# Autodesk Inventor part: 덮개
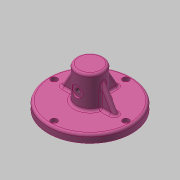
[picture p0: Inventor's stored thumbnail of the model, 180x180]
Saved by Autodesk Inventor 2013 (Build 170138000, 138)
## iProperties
Created: 2017-08
Part Number: 덮개
Material: 알루미늄 6061
Document SubType Name: Modeling
Designer: mduedu
Density: 2.71 g/cm^3
Mass: 336.253 g
Surface Area: 314.323 cm^2
Volume: 124.079 cm^3
Author: mduedu
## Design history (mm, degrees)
sketch "스케치1"
  geometry: C1 r 52.5 at (0, 0); 1 further point
  constraints: 1 centre point, 1 coincident
  dimensions: "d55" = 105 diameter of C1
extrude "돌출1" new body sketch "스케치1" distance "d5" = 10; taper "d6" = 0 deg
sketch "스케치2"
  geometry: C1 r 17 at (0, 0); 1 further point
  constraints: 1 centre point, 1 coincident
  dimensions: "d74" = 34 diameter of C1
extrude "돌출2" join sketch "스케치2" distance "d9" = 40; taper "d10" = 0 deg
sketch "스케치3"
  geometry: C1 r 37 at (0, 0); 1 further point
  constraints: 1 centre point, 1 coincident
  dimensions: "d56" = 74 diameter of C1
extrude "돌출3" join sketch "스케치3" distance "d12" = 8; taper "d13" = 0 deg
sketch "스케치4"
  geometry: C1 r 33 at (0, 0); 1 further point
  constraints: 1 centre point, 1 coincident
  dimensions: "d57" = 66 diameter of C1
extrude "돌출4" cut sketch "스케치4" distance "d16" = 7; taper "d17" = 0 deg
sketch "스케치5"
  geometry: C1 r 9 at (0, 0); 1 further point
  constraints: 1 centre point, 1 coincident
  dimensions: "d18" = 18 diameter of C1
extrude "돌출5" cut sketch "스케치5" distance "d19" = 47; taper "d20" = 0 deg
node "작업 평면1"
sketch "스케치11"
  geometry: L1 (-52.5, -10)-(52.5, -10) reference; 2 further points
  constraints: 1 vertical alignment
  dimensions: "d78" = 28 distance from line of point (0, 18) L1
hole "구멍5" sketch "스케치11" at (0, 18) diameter "d79" = 5.917; stored, may be unused: countersink angle "d83" = 90 deg, drill point angle "d85" = 118 deg; dims "d80" = 6, "d81" = 14, "d82" = 2, "d84" = 8
fillet "모깎기9" dims "d86" = 3
fillet "모깎기5" dims "d40" = 1
sketch "스케치12"
  geometry: C1 r 2.5 at (0, 0); 1 further point
  constraints: 1 centre point, 1 coincident
  dimensions: "d87" = 5 diameter of C1
extrude "돌출6" join sketch "스케치12" distance "d88" = 3; taper "d89" = 0 deg
fillet "모깎기10" dims "d91" = 1
chamfer "모따기1" distance "d41" = 1; stored, may be unused: second distance "d42" = 2, angle "d43" = 45 deg
fillet "모깎기7" dims "d45" = 3
fillet "모깎기8" dims "d46" = 3
sketch "스케치10" dims "d59" = 90
  geometry: 3 further points
  constraints: 2 vertical alignment, 1 coincident, 2 other
hole "구멍4" sketch "스케치10" at (0, 45) diameter "d60" = 4.5; stored, may be unused: countersink angle "d64" = 90 deg, drill point angle "d66" = 118 deg; dims "d61" = 6, "d62" = 8, "d63" = 4.6, "d65" = 8
sketch "스케치13"
  geometry: L1 (52.5, 7)-(52.5, 0) reference; L2 (52.5, 0)-(47.25, 0) reference; L3 (47.25, 0)-(47.25, 5.4) reference; L4 (47.25, 5.4)-(49, 5.4) reference; L5 (49, 5.4)-(49, 10) reference; L6 (49, 10)-(49.5, 10) reference; L7 (-49.5, 10)-(-49, 10) reference; L8 (-49, 10)-(-49, 5.4) reference; L9 (-49, 5.4)-(-47.25, 5.4) reference; L10 (-47.25, 5.4)-(-47.25, 0) reference; L11 (-47.25, 0)-(-52.5, 0) reference; L12 (-52.5, 0)-(-52.5, 7) reference; L13 (-3.5, 46)-(-8, 46) reference; L14 (-9, 45)-(-9, -1) reference; L15 (-9, -1)-(-30, -1) reference; L16 (-33, -4)-(-33, -8) reference; L17 (-33, -8)-(-36, -8) reference; L18 (-36, -8)-(-37, -7) reference; L19 (-37, -7)-(-37, 0) reference; L20 (-37, 0)-(-42.75, 0) reference; L21 (-42.75, 0)-(-42.75, 5.4) reference; L22 (-42.75, 5.4)-(-41, 5.4) reference; L23 (-41, 5.4)-(-41, 10) reference; L24 (-41, 10)-(-20, 10) reference; L25 (-17, 13)-(-17, 47) reference; L26 (-14, 50)-(14, 50) reference; L27 (17, 47)-(17, 13) reference; L28 (20, 10)-(41, 10) reference; L29 (41, 10)-(41, 5.4) reference; L30 (41, 5.4)-(42.75, 5.4) reference; L31 (42.75, 5.4)-(42.75, 0) reference; L32 (42.75, 0)-(37, 0) reference; L33 (37, 0)-(37, -7) reference; L34 (37, -7)-(36, -8) reference; L35 (36, -8)-(33, -8) reference; L36 (33, -8)-(33, -4) reference; L37 (30, -1)-(9, -1) reference; L38 (9, -1)-(9, 45) reference; L39 (8, 46)-(3.5, 46) reference; L40 (2.5, 45)-(2.5, 43) reference; L41 (2.5, 43)-(-2.5, 43) reference; L42 (-2.5, 43)-(-2.5, 45) reference; L43 (17, 40)-(34.321, 10); L44 (-49.5, 10)-(49.5, 10) reference; A1 r 3 centre (49.5, 7) between (52.5, 7) and (49.5, 10) reference; A2 r 3 centre (-49.5, 7) between (-49.5, 10) and (-52.5, 7) reference; A3 r 1 centre (-3.5, 45) between (-2.5, 45) and (-3.5, 46) reference; A4 r 1 centre (-8, 45) between (-8, 46) and (-9, 45) reference; A5 r 3 centre (-30, -4) between (-30, -1) and (-33, -4) reference; A6 r 3 centre (-20, 13) between (-20, 10) and (-17, 13) reference; A7 r 3 centre (-14, 47) between (-14, 50) and (-17, 47) reference; A8 r 3 centre (14, 47) between (17, 47) and (14, 50) reference; A9 r 3 centre (20, 13) between (17, 13) and (20, 10) reference; A10 r 3 centre (30, -4) between (33, -4) and (30, -1) reference; A11 r 1 centre (8, 45) between (9, 45) and (8, 46) reference; A12 r 1 centre (3.5, 45) between (3.5, 46) and (2.5, 45) reference; 1 further point
  constraints: 2 end point, 2 point on line
  dimensions: "d98" = 120 deg angle of L43 L28; "d99" = 30 distance from line of L43.start L44
feature "리브1" sketch "스케치13" dims "d100" = 1, "d101" = 6, "d102" = 0, "d103" = 0, "d104" = 1, "d105" = 1
fillet "모깎기11" dims "d106" = 3
fillet "모깎기12" dims "d107" = 3
node "솔리드1"
pattern_circular "원형 패턴1" dims angle "d68" = 360 deg
pattern_circular "원형 패턴2" dims "d109" = 270 deg
node "절단 모서리 투영1"
